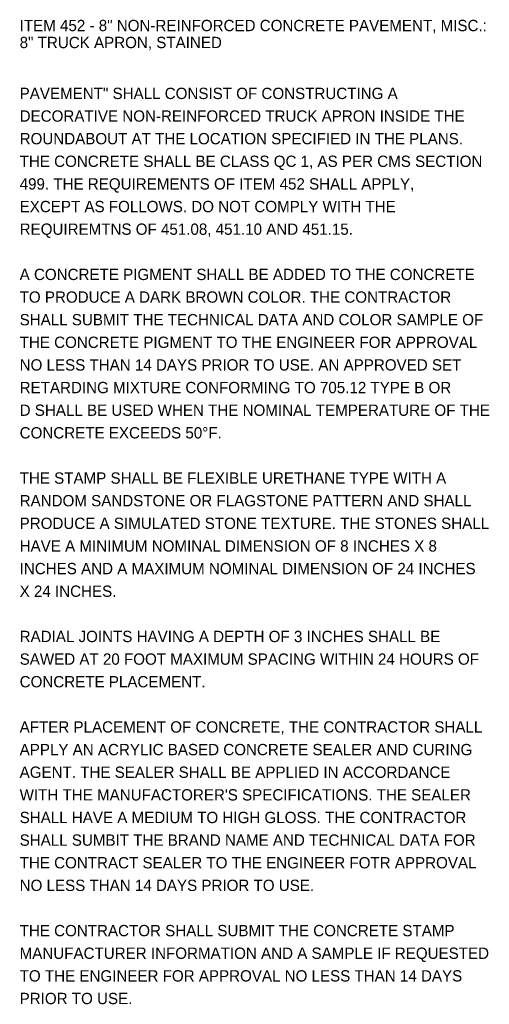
# Model space of a CAD drawing. Extents: x -20.9 to 41.8, y -2.3 to 41.6.
# Drawn here: x -20.89 to -15.08, y 2.33 to 14.51 of the extents above; entities that cross this region are included whole.
import ezdxf

# ---------------------------------------------------------------- set-up
doc = ezdxf.new("R2010")
doc.units = 0
doc.layers.add('SH_Border', color=7, linetype='Continuous')

msp = doc.modelspace()

# ---------------------------------------------------------------- texts
at = {"layer": 'SH_Border'}
for s, p in [('ITEM 452 - 8" NON-REINFORCED CONCRETE PAVEMENT, MISC.:', (-20.891, 14.368)), ('8" TRUCK APRON, STAINED', (-20.891, 14.158)), ('PAVEMENT" SHALL CONSIST OF CONSTRUCTING A', (-20.891, 13.528)), ('DECORATIVE NON-REINFORCED TRUCK APRON INSIDE THE ', (-20.891, 13.248)), ('ROUNDABOUT AT THE LOCATION SPECIFIED IN THE PLANS.', (-20.891, 12.968)), ('THE CONCRETE SHALL BE CLASS QC 1, AS PER CMS SECTION', (-20.891, 12.688)), ('499. THE REQUIREMENTS OF ITEM 452 SHALL APPLY, ', (-20.891, 12.408)), ('EXCEPT AS FOLLOWS. DO NOT COMPLY WITH THE ', (-20.891, 12.128)), ('REQUIREMTNS OF 451.08, 451.10 AND 451.15.', (-20.891, 11.848)), ('A CONCRETE PIGMENT SHALL BE ADDED TO THE CONCRETE', (-20.891, 11.288)), ('TO PRODUCE A DARK BROWN COLOR. THE CONTRACTOR', (-20.891, 11.008)), ('SHALL SUBMIT THE TECHNICAL DATA AND COLOR SAMPLE OF', (-20.891, 10.728)), ('THE CONCRETE PIGMENT TO THE ENGINEER FOR APPROVAL ', (-20.891, 10.448)), ('NO LESS THAN 14 DAYS PRIOR TO USE. AN APPROVED SET', (-20.891, 10.168)), ('RETARDING MIXTURE CONFORMING TO 705.12 TYPE B OR', (-20.891, 9.888)), ('D SHALL BE USED WHEN THE NOMINAL TEMPERATURE OF THE', (-20.891, 9.608)), ('CONCRETE EXCEEDS 50°F. ', (-20.891, 9.328)), ('THE STAMP SHALL BE FLEXIBLE URETHANE TYPE WITH A ', (-20.891, 8.768)), ('RANDOM SANDSTONE OR FLAGSTONE PATTERN AND SHALL', (-20.891, 8.488)), ('PRODUCE A SIMULATED STONE TEXTURE. THE STONES SHALL', (-20.891, 8.208)), ('HAVE A MINIMUM NOMINAL DIMENSION OF 8 INCHES X 8', (-20.891, 7.928)), ('INCHES AND A MAXIMUM NOMINAL DIMENSION OF 24 INCHES ', (-20.891, 7.648)), ('X 24 INCHES.', (-20.891, 7.368)), ('RADIAL JOINTS HAVING A DEPTH OF 3 INCHES SHALL BE ', (-20.891, 6.808)), ('SAWED AT 20 FOOT MAXIMUM SPACING WITHIN 24 HOURS OF', (-20.891, 6.528)), ('CONCRETE PLACEMENT.', (-20.891, 6.248)), ('AFTER PLACEMENT OF CONCRETE, THE CONTRACTOR SHALL', (-20.891, 5.688)), ('APPLY AN ACRYLIC BASED CONCRETE SEALER AND CURING', (-20.891, 5.408)), ('AGENT. THE SEALER SHALL BE APPLIED IN ACCORDANCE ', (-20.891, 5.128)), ("WITH THE MANUFACTORER'S SPECIFICATIONS. THE SEALER", (-20.891, 4.848)), ('SHALL HAVE A MEDIUM TO HIGH GLOSS. THE CONTRACTOR', (-20.891, 4.568)), ('SHALL SUMBIT THE BRAND NAME AND TECHNICAL DATA FOR', (-20.891, 4.288)), ('THE CONTRACT SEALER TO THE ENGINEER FOTR APPROVAL ', (-20.891, 4.008)), ('NO LESS THAN 14 DAYS PRIOR TO USE.', (-20.891, 3.728)), ('THE CONTRACTOR SHALL SUBMIT THE CONCRETE STAMP', (-20.891, 3.168)), ('MANUFACTURER INFORMATION AND A SAMPLE IF REQUESTED', (-20.891, 2.888)), ('TO THE ENGINEER FOR APPROVAL NO LESS THAN 14 DAYS', (-20.891, 2.608)), ('PRIOR TO USE.', (-20.891, 2.328))]:
    msp.add_text(s, height=0.14, dxfattribs=at).set_placement(p)

doc.saveas('drawing.dxf')
